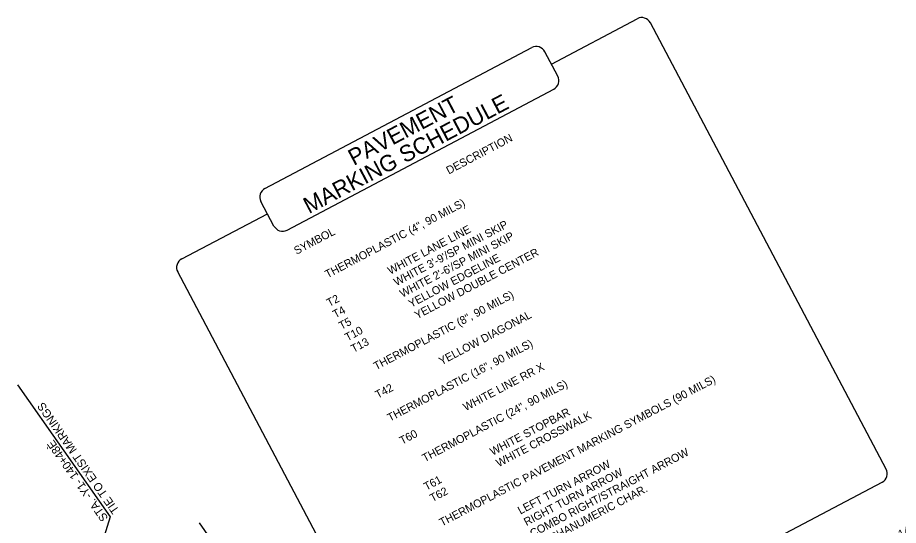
# Model space of a CAD drawing. Extents: x 1487421 to 1489048, y 497792 to 499463.
# Drawn here: x 1487421 to 1488166, y 498768 to 499198 of the extents above; entities that cross this region are included whole.
import ezdxf

# ---------------------------------------------------------------- set-up
doc = ezdxf.new("R2010")
doc.units = 0
for name, color, linetype in [('Default', 7, 'Continuous'), ('Sheet Title CELL', 7, 'Continuous'), ('Text', 7, 'Continuous')]:
    doc.layers.add(name, color=color, linetype=linetype)

msp = doc.modelspace()

# ---------------------------------------------------------------- linework, layer by layer
at = {"layer": 'Sheet Title CELL'}
for p, q in [((1487872.87, 499158.58), (1487945.56, 499196.97)), ((1488156.18, 498815.6), (1487956.61, 499193.55)), ((1487630.55, 499053.27), (1487856.28, 499172.46)), ((1487878.27, 499148.36), (1487867.33, 499169.06)), ((1487649.2, 499018), (1487874.87, 499137.3)), ((1487638.15, 499021.4), (1487627.14, 499042.22)), ((1487560.12, 498993.52), (1487632.64, 499031.81)), ((1487756.31, 498604.46), (1487556.71, 498982.47)), ((1487767.36, 498601.05), (1488152.76, 498804.55))]:
    msp.add_line(p, q, dxfattribs=at)
for centre, start, end in [((1487949.38, 499189.73), 27.83509, 117.83509), ((1487860.1, 499165.23), 27.86524, 117.86524), ((1487871.04, 499144.54), 297.86524, 27.86524), ((1487634.37, 499046.04), 117.86524, 207.86524), ((1487645.38, 499025.23), 207.86524, 297.86524), ((1487563.94, 498986.29), 117.83509, 207.83509), ((1488148.95, 498811.78), 297.83509, 27.83509)]:
    msp.add_arc(centre, 8.18, start, end, dxfattribs=at)
at = {"layer": 'Text'}
for p, q in [((1487421.26, 498887.03), (1487499.6, 498774.97)), ((1487499.6, 498774.97), (1487485.03, 498728.19)), ((1487574.74, 498770.13), (1487641.56, 498674.53))]:
    msp.add_line(p, q, dxfattribs=at)

# ---------------------------------------------------------------- texts
at = {"layer": 'Default'}
for s, height, rotation, p in [('MARKING SCHEDULE', 13.8661, 27.86524, (1487667.72, 499031.46)), ('PAVEMENT', 13.866, 27.86524, (1487705.65, 499072.24)), ('DESCRIPTION', 6.7709, 27.83509, (1487786.07, 499064.97)), ('     THERMOPLASTIC (4", 90 MILS)', 6.7709, 27.83509, (1487672.41, 498971.14)), (' T2                   WHITE LANE LINE', 6.7709, 27.83509, (1487682.68, 498951.68)), (" T4                   WHITE 3'-9'/SP MINI SKIP", 6.7709, 27.83509, (1487687.82, 498941.95)), ('SYMBOL', 6.771, 27.83509, (1487657.25, 498996.95)), (" T5                   WHITE 2'-6'/SP MINI SKIP", 6.7709, 27.83509, (1487692.96, 498932.22)), (' T13                  YELLOW DOUBLE CENTER', 6.7709, 27.83509, (1487703.23, 498912.76)), (' T10                  YELLOW EDGELINE', 6.7709, 27.83509, (1487698.1, 498922.49)), ('     THERMOPLASTIC (8", 90 MILS)', 6.7709, 27.83509, (1487713.51, 498893.3)), (' T42                  YELLOW DIAGONAL', 6.7709, 27.83509, (1487723.78, 498873.84)), (' THERMOPLASTIC (16", 90 MILS)', 6.7709, 27.83509, (1487734.06, 498854.38)), (' T60                  WHITE LINE RR X', 6.7709, 27.83509, (1487744.33, 498834.93)), ('THERMOPLASTIC PAVEMENT MARKING SYMBOLS (90 MILS)', 6.7709, 27.83509, (1487780.29, 498766.82)), ('     THERMOPLASTIC (24", 90 MILS)', 6.7709, 27.83509, (1487754.61, 498815.47)), (' T61                   WHITE STOPBAR', 6.7709, 27.83509, (1487764.88, 498796.01)), (' T62                   WHITE CROSSWALK', 6.7709, 27.83509, (1487770.02, 498786.28)), (' T74                  COMBO RIGHT/STRAIGHT ARROW', 6.7709, 27.83509, (1487800.84, 498727.9)), (' T70                  LEFT TURN ARROW', 6.7709, 27.83509, (1487790.57, 498747.36)), (' T71                  RIGHT TURN ARROW', 6.7709, 27.83509, (1487795.71, 498737.63)), (' T100                 ALPHANUMERIC CHAR.', 6.7709, 27.83509, (1487805.98, 498718.17))]:
    msp.add_text(s, height=height, rotation=rotation, dxfattribs=at).set_placement(p)
at = {"layer": 'Text'}
for s, rotation, p in [('TIE TO EXIST MARKINGS', 124.95537, (1487507.48, 498780.69)), ('STA. -Y1- 140+48È', 124.95537, (1487498.16, 498774.17)), ('STA. -L- 14+28È', 27.83501, (1488135.4, 498739.14))]:
    msp.add_text(s, height=7, rotation=rotation, dxfattribs=at).set_placement(p)

doc.saveas('drawing.dxf')
